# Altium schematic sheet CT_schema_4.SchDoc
size 287 x 163 mm
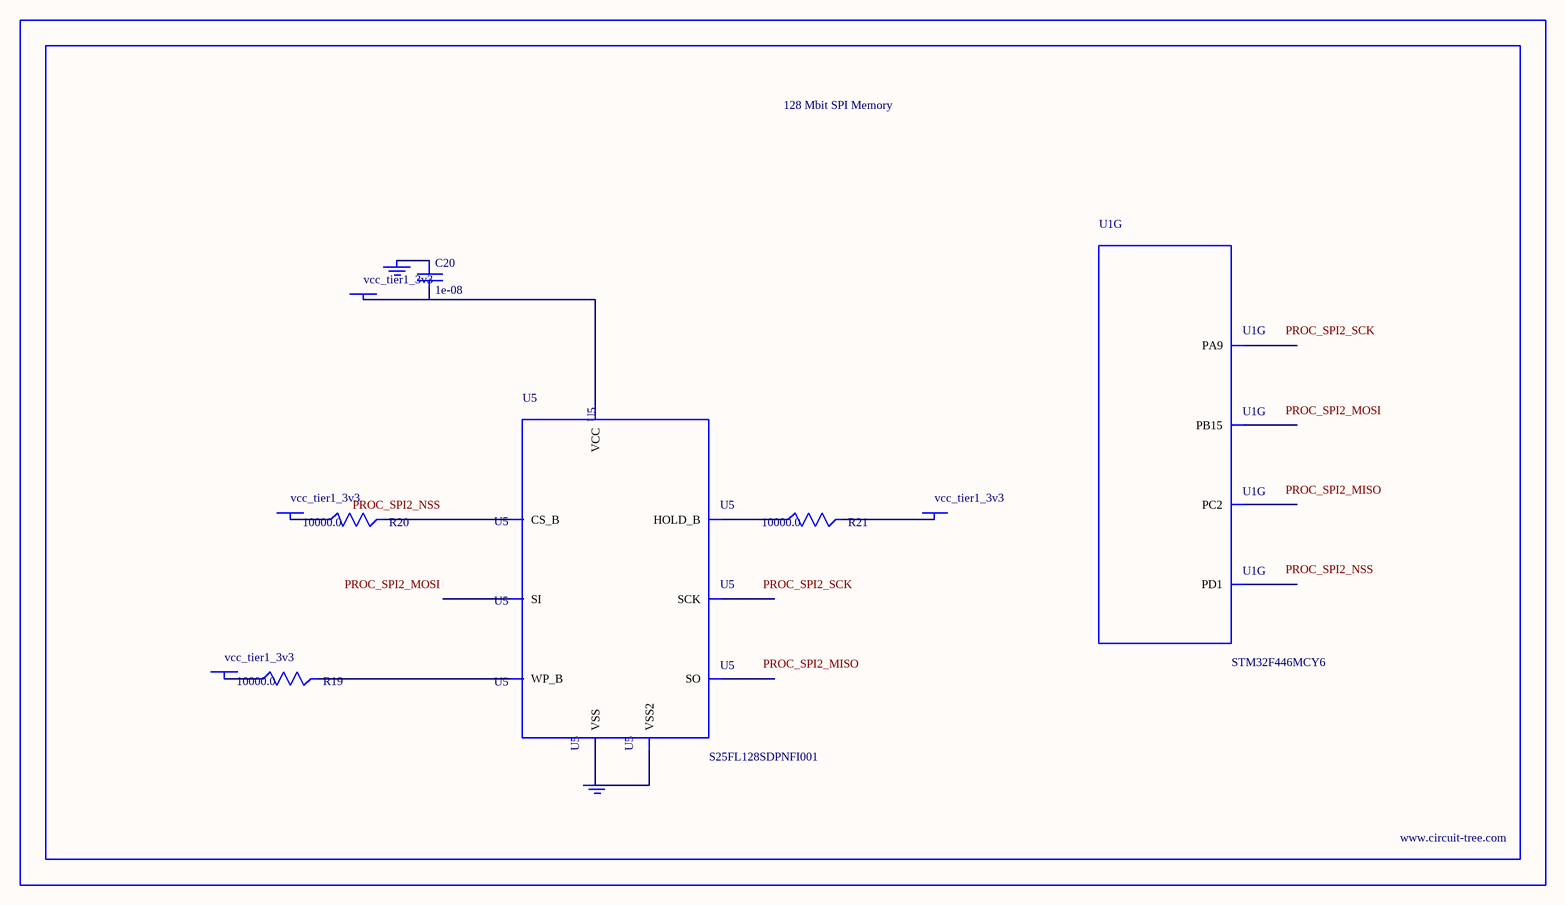
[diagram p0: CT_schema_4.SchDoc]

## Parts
BORDER3  (no value)
C20  1e-08  [C0402]
GND_INSTANCE_3_0  (no value)
GND_INSTANCE_3_1  (no value)
POWER_INSTANCE_3_0  vcc_tier1_3v3
POWER_INSTANCE_3_1  vcc_tier1_3v3
POWER_INSTANCE_3_2  vcc_tier1_3v3
POWER_INSTANCE_3_3  vcc_tier1_3v3
R19  10000.0  [R0603]
R20  10000.0  [R0603]
R21  10000.0  [R0603]
U1  STM32F446MCY6  [WLCSP81]  (part G of 9)
U5  S25FL128SDPNFI001  [WNG008]

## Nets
NetC20_1: C20.1 GND_INSTANCE_3_0.0(GND)
NetC20_2: C20.2 POWER_INSTANCE_3_3.0(PWR) U5.8(VCC)
NetGND_INSTANCE_3_1_0: GND_INSTANCE_3_1.0(GND) U5.4(VSS) U5.PAD(VSS2)
NetPOWER_INSTANCE_3_0_0: POWER_INSTANCE_3_0.0(PWR) R20.1
NetPOWER_INSTANCE_3_1_0: POWER_INSTANCE_3_1.0(PWR) R19.1
NetPOWER_INSTANCE_3_2_0: POWER_INSTANCE_3_2.0(PWR) R21.2
NetR19_2: R19.2 U5.3(WP_B)
NetR20_2: R20.2 U5.1(CS_B)
NetR21_1: R21.1 U5.7(HOLD_B)

Not connected (* = marked no-connect by the designer): U1 C4(PD1) E8(PC2) F4(PA9) G3(PB15); U5 2(SO) 5(SI) 6(SCK)

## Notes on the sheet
- Labels drawn without touching a wire or pin: PROC_SPI2_MISO, PROC_SPI2_MOSI, PROC_SPI2_NSS, PROC_SPI2_SCK

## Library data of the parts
BORDER3 = BORDER_PAGE3
C20 = C0402C103K3RAC
GND_INSTANCE_3_0 GND_INSTANCE_3_1 = GND
POWER_INSTANCE_3_0-POWER_INSTANCE_3_3 = PWR
R19-R21 = RC0603JR-0710KL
